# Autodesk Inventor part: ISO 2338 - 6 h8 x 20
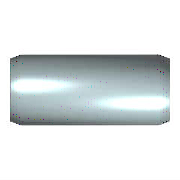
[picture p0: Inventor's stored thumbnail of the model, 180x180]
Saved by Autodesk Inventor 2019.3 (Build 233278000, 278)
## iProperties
Created: 2018-01
Part Number: ISO 2338 - 6 h8 x 20
Material: Nerezová ocel, austenitická
Description: Válcové kolíky, nekalené
Document SubType Name: Modeling
Standard: ISO 2338
Designer: B-hon
Standards Organization: CSN
Language: cs-CZ
Size Designation: 6 h8 x 20
Categories: <MemberInstance><Categories><Category DisplayName="Spojovací materiál" InternalName="e4da775c-781d-43d5-af7c-5136215cf5a6" Mnemonic="FSTN"><Category DisplayName
Density: 8 g/cm^3
Appearance: Pololeštěná
IsCustomPart: 0
Author: B-hon
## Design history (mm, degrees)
sketch "Náčrt"
  geometry: C1 r 3 at (0, 0); 1 further point
  constraints: 1 centre point, 1 coincident
  dimensions: "d1" = 6 diameter of C1 (= NND)
extrude "Těleso" new body sketch "Náčrt" distance "d2" = 20 (= NLG); taper "d3" = 0 deg
chamfer "Náčrt2" distance "d8" = 1.2 (= PHH); stored, may be unused: angle "d9" = 15 deg (= FAWI), second distance "d12" = 1.2 (= PHH)
body "Solid1"
chamfer "Zkosení1" distance "d4" = 1.2 (= PHH); stored, may be unused: angle "d5" = 15 deg (= FAWI), second distance "d11" = 1.2 (= PHH)
other parameters: "NND" = 6 [user parameter; used in 1 equation term], "NLG" = 20 [user parameter; used in 1 equation term], "PHH" = 1.2 [user parameter; used in 4 equation terms], "FAWI" = 15 deg [user parameter; used in 2 equation terms], "d13" = 0, "d15" = 0, "d16" = 0, "KAH" = 0 [user parameter]
